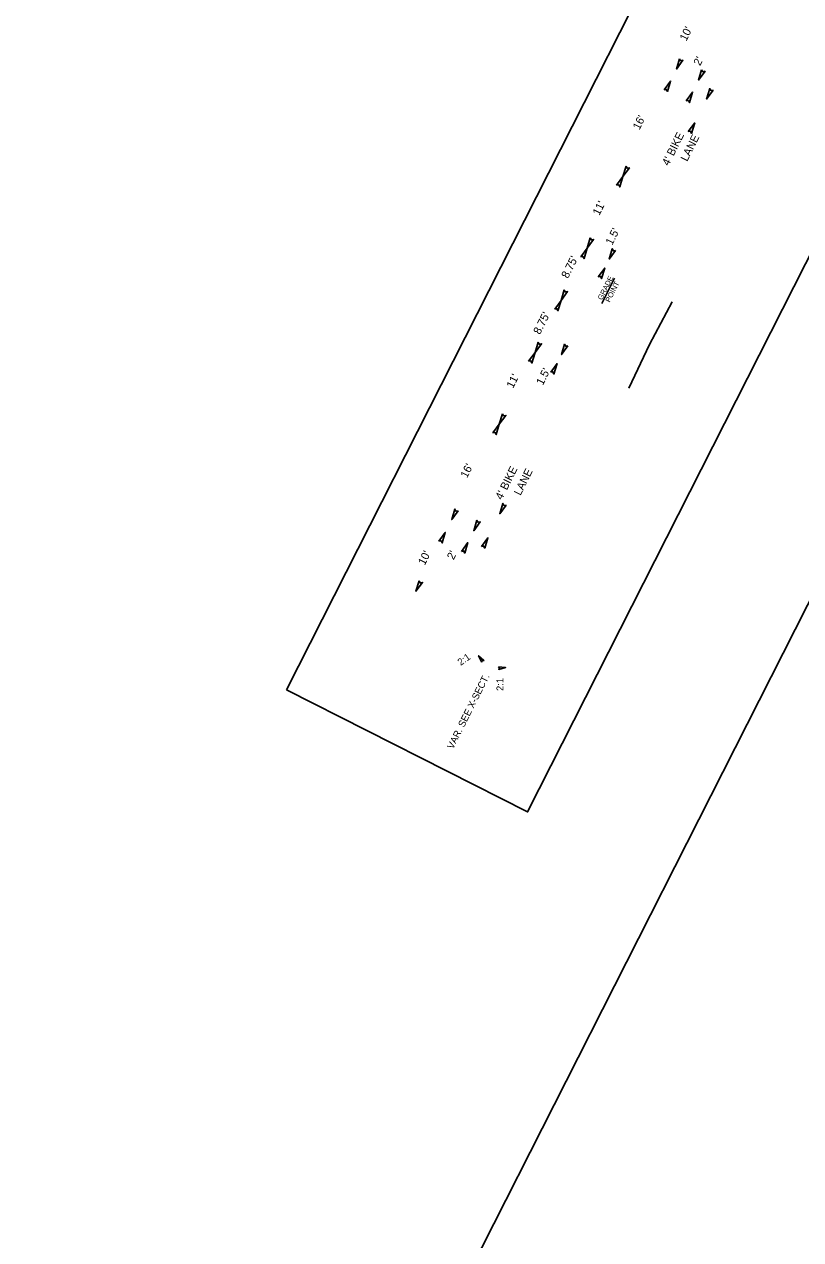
# Model space of a CAD drawing. Extents: x 1974386 to 1979988, y 776712 to 784860.
# Drawn here: x 1975786 to 1976485, y 781294 to 782388 of the extents above; entities that cross this region are included whole.
import ezdxf

# ---------------------------------------------------------------- set-up
doc = ezdxf.new("R2010")
doc.units = 0
for name, color, linetype in [('Default', 7, 'Continuous'), ('Old_Level_11', 7, 'Continuous'), ('Old_Level_3', 7, 'Continuous'), ('Old_Level_4', 7, 'Continuous')]:
    doc.layers.add(name, color=color, linetype=linetype)

msp = doc.modelspace()

# ---------------------------------------------------------------- linework, layer by layer
at = {"layer": 'Default'}
msp.add_lwpolyline([(1978010, 784859.9), (1974385.9, 777715.1), (1976364, 776711.7), (1979988.1, 783856.5)], close=True, dxfattribs=at)
at = {"layer": 'Old_Level_11'}
for q in [(1976369.4, 782138.1), (1976330.6, 782060.3)]:
    msp.add_line((1976349.2, 782099.6), q, dxfattribs=at)
for points in [[(1976376.2, 782356.7), (1976373.4, 782347.4), (1976379.2, 782355.3), (1976377.1, 782354.9)], [(1976376.2, 782356.7), (1976373.4, 782347.4), (1976379.2, 782355.3), (1976377.1, 782354.9)], [(1976362.2, 782328.8), (1976368, 782336.6), (1976365.2, 782327.2), (1976364.2, 782329.1)], [(1976362.2, 782328.8), (1976368, 782336.6), (1976365.2, 782327.2), (1976364.2, 782329.1)], [(1976396, 782346.8), (1976393.2, 782337.5), (1976399.1, 782345.4), (1976397, 782345)], [(1976396, 782346.8), (1976393.2, 782337.5), (1976399.1, 782345.4), (1976397, 782345)], [(1976382.1, 782318.9), (1976387.9, 782326.7), (1976385.1, 782317.3), (1976384.1, 782319.2)], [(1976382.1, 782318.9), (1976387.9, 782326.7), (1976385.1, 782317.3), (1976384.1, 782319.2)], [(1976406.3, 782328.3), (1976400.5, 782320.4), (1976403.3, 782329.8), (1976404.3, 782328)], [(1976406.3, 782328.3), (1976400.5, 782320.4), (1976403.3, 782329.8), (1976404.3, 782328)], [(1976384, 782291.1), (1976389.8, 782298.9), (1976387, 782289.5), (1976386, 782291.4)], [(1976384, 782291.1), (1976389.8, 782298.9), (1976387, 782289.5), (1976386, 782291.4)], [(1976328, 782260.1), (1976325.1, 782250.7), (1976331, 782258.6), (1976328.9, 782258.3)], [(1976328, 782260.1), (1976325.1, 782250.7), (1976331, 782258.6), (1976328.9, 782258.3)], [(1976319.4, 782242.9), (1976325.1, 782250.7), (1976322.3, 782241.3), (1976321.4, 782243.2)], [(1976319.4, 782242.9), (1976325.1, 782250.7), (1976322.3, 782241.3), (1976321.4, 782243.2)], [(1976295.8, 782195.7), (1976293, 782186.3), (1976298.8, 782194.2), (1976296.8, 782193.9)], [(1976295.8, 782195.7), (1976293, 782186.3), (1976298.8, 782194.2), (1976296.8, 782193.9)], [(1976287.2, 782178.4), (1976293, 782186.3), (1976290.2, 782176.9), (1976289.2, 782178.8)], [(1976287.2, 782178.4), (1976293, 782186.3), (1976290.2, 782176.9), (1976289.2, 782178.8)], [(1976318.6, 782184.3), (1976312.8, 782176.4), (1976315.6, 782185.8), (1976316.6, 782184)], [(1976318.6, 782184.3), (1976312.8, 782176.4), (1976315.6, 782185.8), (1976316.6, 782184)], [(1976303, 782160.5), (1976308.8, 782168.4), (1976306, 782158.9), (1976305, 782160.8)], [(1976303, 782160.5), (1976308.8, 782168.4), (1976306, 782158.9), (1976305, 782160.8)], [(1976272.4, 782148.7), (1976269.5, 782139.3), (1976275.4, 782147.2), (1976273.3, 782146.9)], [(1976272.4, 782148.7), (1976269.5, 782139.3), (1976275.4, 782147.2), (1976273.3, 782146.9)], [(1976263.8, 782131.5), (1976269.5, 782139.3), (1976266.7, 782129.9), (1976265.8, 782131.8)], [(1976263.8, 782131.5), (1976269.5, 782139.3), (1976266.7, 782129.9), (1976265.8, 782131.8)], [(1976248.9, 782101.7), (1976246.1, 782092.4), (1976251.9, 782100.3), (1976249.9, 782099.9)], [(1976248.9, 782101.7), (1976246.1, 782092.4), (1976251.9, 782100.3), (1976249.9, 782099.9)], [(1976275.7, 782098.4), (1976270, 782090.5), (1976272.7, 782099.9), (1976273.7, 782098.1)], [(1976275.7, 782098.4), (1976270, 782090.5), (1976272.7, 782099.9), (1976273.7, 782098.1)], [(1976240.3, 782084.5), (1976246.1, 782092.4), (1976243.3, 782082.9), (1976242.3, 782084.8)], [(1976240.3, 782084.5), (1976246.1, 782092.4), (1976243.3, 782082.9), (1976242.3, 782084.8)], [(1976260.2, 782074.6), (1976265.9, 782082.5), (1976263.1, 782073), (1976262.2, 782074.9)], [(1976260.2, 782074.6), (1976265.9, 782082.5), (1976263.1, 782073), (1976262.2, 782074.9)], [(1976216.7, 782037.3), (1976213.9, 782027.9), (1976219.8, 782035.8), (1976217.7, 782035.5)], [(1976216.7, 782037.3), (1976213.9, 782027.9), (1976219.8, 782035.8), (1976217.7, 782035.5)], [(1976208.2, 782020.1), (1976213.9, 782027.9), (1976211.1, 782018.5), (1976210.2, 782020.4)], [(1976208.2, 782020.1), (1976213.9, 782027.9), (1976211.1, 782018.5), (1976210.2, 782020.4)], [(1976220.1, 781955.2), (1976214.3, 781947.3), (1976217.1, 781956.7), (1976218.1, 781954.9)], [(1976220.1, 781955.2), (1976214.3, 781947.3), (1976217.1, 781956.7), (1976218.1, 781954.9)], [(1976176.8, 781949.9), (1976171.1, 781942.1), (1976173.9, 781951.5), (1976174.8, 781949.6)], [(1976176.8, 781949.9), (1976171.1, 781942.1), (1976173.9, 781951.5), (1976174.8, 781949.6)], [(1976193.7, 781941.5), (1976190.9, 781932.1), (1976196.8, 781940), (1976194.7, 781939.7)], [(1976193.7, 781941.5), (1976190.9, 781932.1), (1976196.8, 781940), (1976194.7, 781939.7)], [(1976159.5, 781922.6), (1976165.3, 781930.5), (1976162.5, 781921.1), (1976161.5, 781923)], [(1976159.5, 781922.6), (1976165.3, 781930.5), (1976162.5, 781921.1), (1976161.5, 781923)], [(1976179.8, 781913.5), (1976185.5, 781921.4), (1976182.8, 781912), (1976181.8, 781913.9)], [(1976179.8, 781913.5), (1976185.5, 781921.4), (1976182.8, 781912), (1976181.8, 781913.9)], [(1976197.8, 781917.9), (1976203.6, 781925.8), (1976200.8, 781916.4), (1976199.8, 781918.3)], [(1976197.8, 781917.9), (1976203.6, 781925.8), (1976200.8, 781916.4), (1976199.8, 781918.3)], [(1976141.7, 781887), (1976138.9, 781877.7), (1976144.8, 781885.6), (1976142.7, 781885.2)], [(1976141.7, 781887), (1976138.9, 781877.7), (1976144.8, 781885.6), (1976142.7, 781885.2)], [(1976198.2, 781813.9), (1976195.2, 781819.6), (1976200, 781815.3), (1976198.6, 781815.2)], [(1976213.2, 781809.5), (1976219.6, 781809), (1976213.4, 781807.3), (1976214.1, 781808.5)]]:
    msp.add_lwpolyline(points, close=True, dxfattribs=at)
at = {"layer": 'Old_Level_3'}
msp.add_line((1976306.3, 782136.4), (1976317.7, 782159.3), dxfattribs=at)
at = {"layer": 'Old_Level_4'}
msp.add_lwpolyline([(1976022.4, 781789.1), (1976408.2, 782549.8), (1976625.1, 782439.7), (1976239.3, 781679.1)], close=True, dxfattribs=at)

# ---------------------------------------------------------------- texts
at = {"layer": 'Old_Level_11'}
for s, height, rotation, p in [("10'", 7.2, 63.4744, (1976382.2, 782372)), ("2'", 7.2, 63.4744, (1976394.6, 782349.8)), ("16'", 7.2, 63.4744, (1976340, 782292.2)), ("4' BIKE ", 7.2, 63.4744, (1976366.3, 782259.8)), ('LANE', 7.2, 63.4744, (1976383, 782263.7)), ("11'", 7.2, 63.4744, (1976303.9, 782215.1)), ("1.5'", 7.2, 63.4744, (1976315.5, 782188.4)), ("8.75'", 7.2, 63.4744, (1976275.7, 782158.5)), ('GRADE', 4.71, 63.4744, (1976306.4, 782139.2)), ('POINT', 4.71, 63.4744, (1976313.3, 782137.1)), ("8.75'", 7.2, 63.4744, (1976250.5, 782108.1)), ("1.5'", 7.2, 63.4744, (1976253.1, 782062.4)), ("11'", 7.2, 63.4744, (1976226.3, 782059.6)), ("16'", 7.2, 63.4744, (1976184.9, 781978.9)), ("4' BIKE ", 7.2, 63.4744, (1976216.3, 781959.3)), ('LANE', 7.2, 63.4744, (1976233, 781963.2)), ("10'", 7.2, 63.4744, (1976146.8, 781900.5)), ("2'", 7.2, 63.4744, (1976172.8, 781905.4)), ('2:1', 6.28, 35.2642, (1976179.1, 781810.4)), ('VAR. SEE X-SECT.', 6.276, 63.4744, (1976172.3, 781735.1)), ('2:1', 6.28, 90.4751, (1976217.7, 781788))]:
    msp.add_text(s, height=height, rotation=rotation, dxfattribs=at).set_placement(p)

doc.saveas('drawing.dxf')
